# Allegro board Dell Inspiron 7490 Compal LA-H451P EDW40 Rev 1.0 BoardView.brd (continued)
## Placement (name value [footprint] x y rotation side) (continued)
CV327  220P_0201_25V7K  [C_0201]  119.01 53.18 0 top
CV390  1U_0201_6.3V6M  [C_0201]  110.88 51.73 315 top
CV391  1U_0201_6.3V6M  [C_0201]  104.26 52.87 180 top
CV392  4.7U_0201_6.3V6M  [C_0201]  109.02 50.94 225 top
CV393  4.7U_0201_6.3V6M  [C_0201]  108.2 46.64 135 top
CV394  0.1U_0201_10V6K  [C_0201]  105.95 63.86 0 top
CV395  4.7U_0201_6.3V6M  [C_0201]  104.19 67.5 45 top
CV396  22U_0603_6.3V6M  [C_0603]  106.05 64.87 45 top
CV397  0.1U_0201_10V6K  [C_0201]  122.98 38.45 225 top
CV398  0.1U_0201_10V6K  [C_0201]  103.25 63.42 270 top
CV399  1U_0201_6.3V6M  [C_0201]  97.62 62.92 90 top
CV400  1U_0201_6.3V6M  [C_0201]  103.83 48.22 45 top
CV401  1U_0201_6.3V6M  [C_0201]  103.02 49.03 45 top
CV402  1U_0201_6.3V6M  [C_0201]  104.25 47.78 45 top
CV403  10U_0402_6.3V6M  [C_0402]  98.85 39.79 180 top
CV404  10U_0402_6.3V6M  [C_0402]  98.85 38.87 180 top
CV405  22U_0603_6.3V6M  [C_0603]  99.09 37.83 180 top
CV406  22U_0603_6.3V6M  [C_0603]  101.92 51.66 0 top
CV597  10U_0603_6.3V6M  [C_0603]  16.21 47.35 270 top
CV598  0.1U_0201_16V6K  [C_0201]  15.32 46.87 270 top
CV599  0.1U_01005_10V6K  [C_01005]  21.72 42.93 180 bottom
CV600  0.1U_01005_10V6K  [C_01005]  15.58 45.23 180 top
CV601  22U_0603_6.3V6M  [C_0603]  77.74 72.91 315 top
CV602  22U_0603_6.3V6M  [C_0603]  79.47 74.66 315 top
CV603  10U_0603_6.3V6M  [C_0603]  78.6 73.8 315 top
CV604  10U_0603_6.3V6M  [C_0603]  80.35 75.51 315 top
CV605  10U_0603_6.3V6M  [C_0603]  82.34 77.49 315 top
CV606  10U_0603_6.3V6M  [C_0603]  81.49 76.64 315 top
CV607  10U_0603_6.3V6M  [C_0603]  83.2 78.34 315 top
CV608  10U_0603_6.3V6M  [C_0603]  84.06 79.17 315 top
CV609  1U_0201_6.3V6M  [C_0201]  81.74 67.76 45 bottom
CV610  1U_0201_6.3V6M  [C_0201]  88.34 75.55 270 bottom
CV611  1U_0201_6.3V6M  [C_0201]  98.77 40.54 180 top
CV612  1U_0201_6.3V6M  [C_0201]  94.11 72.21 225 bottom
CV613  1U_0201_6.3V6M  [C_0201]  88.65 65.62 135 bottom
CV614  1U_0201_6.3V6M  [C_0201]  94.64 69.69 45 bottom
CV615  1U_0201_6.3V6M  [C_0201]  87.74 66.97 45 bottom
CV616  1U_0201_6.3V6M  [C_0201]  90.14 75.46 45 bottom
CV617  1U_0201_6.3V6M  [C_0201]  87.24 73.29 270 bottom
CV618  1U_0201_6.3V6M  [C_0201]  86.72 63.5 270 bottom
CV633  2200P_0201_25V7K  [C_0201]  37.37 76.6 180 top
CV651  2200P_0201_16V7K  [C_0201]  36.04 76.6 180 top
CV701  22U_0603_6.3V6M  [C_0603]  81.9 34.23 45 top
CV702  22U_0603_6.3V6M  [C_0603]  80.18 35.95 45 top
CV703  10U_0603_6.3V6M  [C_0603]  82.75 33.39 45 top
CV704  10U_0603_6.3V6M  [C_0603]  81.03 35.1 45 top
CV705  10U_0603_6.3V6M  [C_0603]  78.25 37.87 45 top
CV706  10U_0603_6.3V6M  [C_0603]  77.4 38.71 45 top
CV707  10U_0603_6.3V6M  [C_0603]  76.55 39.57 45 top
CV708  10U_0603_6.3V6M  [C_0603]  75.7 40.42 45 top
CV709  1U_0201_6.3V6M  [C_0201]  93.4 42.98 135 bottom
CV710  1U_0201_6.3V6M  [C_0201]  83.12 45.26 315 bottom
CV711  1U_0201_6.3V6M  [C_0201]  84.54 43.84 135 bottom
CV712  1U_0201_6.3V6M  [C_0201]  85.88 45.79 315 bottom
CV713  1U_0201_6.3V6M  [C_0201]  80.55 43.29 45 bottom
CV714  1U_0201_6.3V6M  [C_0201]  78.95 42.32 315 bottom
CV715  1U_0201_6.3V6M  [C_0201]  83.79 41.42 45 bottom
CV716  1U_0201_6.3V6M  [C_0201]  85.61 44.02 315 bottom
CV717  1U_0201_6.3V6M  [C_0201]  82.84 43.06 135 bottom
CV718  1U_0201_6.3V6M  [C_0201]  86.3 47.83 90 bottom
CV741  820P_0201_25V7K  [C_0201]  79.97 37.56 225 top
CV754  820P_0201_25V7K  [C_0201]  79.58 37.95 225 top
CV755  1U_0201_6.3V6M  [C_0201]  116.17 49.62 0 top
CV756  0.1U_0201_6.3V6K  [C_0201]  98.86 65.36 315 top
CV757  0.1U_0201_6.3V6K  [C_0201]  98.95 64.37 225 top
CV759  1U_0201_6.3V6M  [C_0201]  84.58 48.06 225 bottom
CV760  1U_0201_6.3V6M  [C_0201]  94.17 41.95 135 bottom
CV761  1U_0201_6.3V6M  [C_0201]  90.78 41.32 0 bottom
CV762  1U_0201_6.3V6M  [C_0201]  86.37 49.74 315 bottom
CV763  1U_0201_6.3V6M  [C_0201]  95.81 70.75 45 bottom
CV764  1U_0201_6.3V6M  [C_0201]  86.02 65.51 270 bottom
CV765  1U_0201_6.3V6M  [C_0201]  91.69 71.26 225 bottom
CV766  1U_0201_6.3V6M  [C_0201]  92.96 72.51 45 bottom
CV767  100P_0201_25V8J  [C_0201]  114.46 51.37 135 top
CV768  0.1U_0201_6.3V6K  [C_0201]  108.63 47.04 135 top
CV769  0.1U_0201_6.3V6K  [C_0201]  109.43 50.52 225 top
CV770  100P_0201_25V8J  [C_0201]  107.45 51.87 315 top
CV771  100P_0201_25V8J  [C_0201]  104.96 63.5 270 top
CV772  100P_0201_25V8J  [C_0201]  93.57 62.75 180 top
CV773  0.1U_0201_6.3V6K  [C_0201]  93.57 63.33 180 top
CV774  0.1U_0201_10V6K  [C_0201]  105.38 66.25 45 top
CV775  100P_0201_25V8J  [C_0201]  104.99 66.67 45 top
CV776  0.1U_0201_10V6K  [C_0201]  102.87 67.9 90 top
CV777  100P_0201_25V8J  [C_0201]  102.39 65.67 315 top
CV778  0.1U_0201_10V6K  [C_0201]  98.13 65.19 225 top
CV779  100P_0201_25V8J  [C_0201]  98.52 64.77 225 top
CV780  0.1U_0201_6.3V6K  [C_0201]  102.68 63.4 270 top
CV781  10P_0201_25V8  [C_0201]  103.15 64.04 90 top
CV782  100P_0201_25V8J  [C_0201]  99.37 54.42 90 top
CV783  100P_0201_25V8J  [C_0201]  103.77 64.05 0 top
CV784  100P_0201_25V8J  [C_0201]  103.82 63.45 270 top
CV785  2200P_0201_16V7K  [C_0201]  98.76 53.67 0 top
CV786  100P_0201_25V8J  [C_0201]  120.78 51.64 90 top
CV787  0.1U_0201_6.3V6K  [C_0201]  121.35 51.64 90 top
CV788  100P_0201_25V8J  [C_0201]  116.13 51.93 270 top
CV789  100P_0201_25V8J  [C_0201]  120.06 54.96 0 top
CV930  0.1U_01005_10V6K  [C_01005]  28.11 38.81 0 top
CV931  10P_0201_25V8  [C_0201]  107.79 46.24 135 top
CV932  10P_0201_25V8  [C_0201]  98.77 41.1 180 top
CV933  10P_0201_25V8  [C_0201]  108.28 64.09 180 top
CV934  22U_0603_6.3V6M  [C_0603]  102.43 50.45 0 top
CV935  22U_0603_6.3V6M  [C_0603]  114.47 53.81 180 top
CW11  10U_0402_10V6M  [C_0402]  122.35 72.47 180 top
CW12  10P_0201_25V8  [C_0201]  122.19 73.22 180 top
CW13  0.1U_0201_10V6K  [C_0201]  137.21 77.02 270 top
CW14  1U_0201_6.3V6M  [C_0201]  138.38 77.02 270 top
CW15  10U_0402_10V6M  [C_0402]  139.13 77.19 270 top
CW16  10P_0201_25V8  [C_0201]  122.19 74.39 180 top
CW17  0.1U_0201_10V6K  [C_0201]  137.79 77.02 270 top
CW18  1U_0201_6.3V6M  [C_0201]  122.19 73.8 180 top
CZ1  1U_0201_6.3V6M  [C_0201]  142.21 29.15 180 bottom
CZ2  1U_0201_6.3V6M  [C_0201]  142.2 27.82 180 bottom
CZ3  0.1U_0201_10V6K  [C_0201]  142.21 29.71 180 bottom
CZ4  0.1U_0201_10V6K  [C_0201]  142.21 28.59 180 bottom
CZ5  0.1U_0201_10V6K  [C_0201]  146.69 30.36 0 bottom
CZ6  1000P_0201_16V7K  [C_0201]  146.69 29.8 0 bottom
CZ7  220P_0201_25V7K  [C_0201]  146.69 29.24 0 bottom
CZ8  0.1U_0201_10V6K  [C_0201]  146.71 27.82 0 bottom
CZ9  1U_0201_6.3V6M  [C_0201]  114.6 29.49 0 top
CZ10  1U_0201_6.3V6M  [C_0201]  113.22 29.49 180 top
CZ11  0.1U_0201_10V6K  [C_0201]  102.26 21.44 270 top
CZ12  0.1U_0201_10V6K  [C_0201]  112.33 24.6 180 top
CZ13  1U_0201_6.3V6M  [C_0201]  89.54 23.41 180 top
CZ14  1U_0201_6.3V6M  [C_0201]  91.94 22.72 270 top
CZ15  0.1U_0201_10V6K  [C_0201]  90.52 27.6 90 top
CZ16  470P_0201_25V7K  [C_0201]  91.07 27.6 90 top
CZ17  4700P_0402_25V7K  [C_0402]  91.81 27.64 90 top
CZ18  0.1U_0201_10V6K  [C_0201]  92.57 27.63 90 top
CZ19  1U_0201_6.3V6M  [C_0201]  121.02 48.76 90 bottom
CZ20  0.1U_0201_10V6K  [C_0201]  121.65 48.76 90 bottom
CZ21  1U_0201_6.3V6M  [C_0201]  123.6 48.13 270 bottom
CZ22  1000P_0201_16V7K  [C_0201]  122.64 44.26 0 bottom
CZ23  0.1U_0201_10V6K  [C_0201]  122.64 43.13 0 bottom
CZ38  1U_0201_6.3V6M  [C_0201]  154.97 61.6 180 top
CZ39  1U_0201_6.3V6M  [C_0201]  153.2 61.58 0 top
CZ40  0.1U_0201_10V6K  [C_0201]  148.29 49.77 180 top
CZ218  2.2U_0201_6.3V6M  [C_0201]  36.04 13.44 180 top
CZ219  0.1U_0201_10V6K  [C_0201]  151.52 60.45 180 top
CZ220  0.1U_0201_10V6K  [C_0201]  133.37 71.68 180 top
CZ221  1U_0201_6.3V6M  [C_0201]  135.17 70.2 0 top
CZ223  1U_0201_6.3V6M  [C_0201]  134.56 71.68 180 top
CZ224  1000P_0201_16V7K  [C_0201]  139 71.43 0 top
CZ225  0.1U_0201_10V6K  [C_0201]  186.9 26.92 0 top
CZ226  100P_0201_25V8J  [C_0201]  89.96 27.6 90 top
CZ227  0.1U_0201_10V6K  [C_0201]  138.7 74.25 90 top
CZ228  100P_0201_25V8J  [C_0201]  138.14 74.25 90 top
CZ229  100P_0201_25V8J  [C_0201]  122.64 43.69 0 bottom
CZ230  100P_0201_25V8J  [C_0201]  148.78 30.11 270 bottom
CZ231  100P_0201_25V8J  [C_0201]  148.15 29.23 90 bottom
CZ232  100P_0201_25V8J  [C_0201]  110.58 24.51 90 top
CZ233  100P_0201_25V8J  [C_0201]  148.94 51.23 0 top
CZ234  0.1U_0201_10V6K  [C_0201]  43.98 45.91 270 top
CZ235  1000P_0201_16V7K  [C_0201]  47 45.68 90 top
CZ236  1U_0201_6.3V6M  [C_0201]  48.01 40.63 0 top
CZ237  0.1U_0201_16V6K  [C_0201]  47.41 41.01 270 top
CZ238  10P_0201_25V8  [C_0201]  89.4 27.6 90 top
CZ239  10P_0201_25V8  [C_0201]  139.23 73.65 0 top
D2  BAT54CTB SOT-523  [BAT54CT-7-F_SOT523-3]  58.34 35.35 0 top
D3  -  [RB751S40T1G_SOD523-2]  2.39 76.15 270 bottom
D4  BAT54CTB SOT-523  [BAT54CT-7-F_SOT523-3]  35.45 62.2 270 bottom
D5  -  [RB551V-30_SOD323-2]  121.54 6.57 90 top
D8  RB751S40T1G_SOD523-2  [RB520SM-30T2R_EMD2-2]  59.35 24.95 270 top
D9  BAS516_SC79-2  [1N4148WT-7_SOD523-2]  40.54 77.41 0 top
D462  -  [RB751S40T1G_SOD523-2]  38.9 33.96 0 top
D463  BAT54CTB SOT-523  [BAT54CT-7-F_SOT523-3]  35.73 67.53 0 top
D464  -  [RB751S40T1G_SOD523-2]  15.06 68.81 90 top
D465  -  [RB751S40T1G_SOD523-2]  13.87 70.31 270 top
DB3  -  [RB520SM-30T2R_EMD2-2]  25.67 7.72 180 bottom
DB4  -  [BAT54HT1G_SOD323-2]  24.56 4.37 90 bottom
DS1  PUSB3F96_DFN2510A-10-10-X  [AZ1045-04F_DFN2510P10E-10-9]  25.33 4.75 90 top
DT4  CEST23NC24VU 3P C/A SOT23 BATT  [L30ESD24VC3-2_SOT23-3]  16.47 58.2 90 top
DT5  -  [DESD3V3Z1BCSF-7_X2-DSN0603-2-2]  12.91 64.58 270 bottom
DT6  -  [DESD3V3Z1BCSF-7_X2-DSN0603-2-2]  12.91 65.16 90 bottom
DT9  -  [DESD3V3Z1BCSF-7_X2-DSN0603-2-2]  12.91 68.51 270 bottom
DT10  -  [DESD3V3Z1BCSF-7_X2-DSN0603-2-2]  12.91 69.1 90 bottom
DT13  -  [DESD3V3Z1BCSF-7_X2-DSN0603-2-2]  12.91 62.61 270 bottom
DT14  -  [DESD3V3Z1BCSF-7_X2-DSN0603-2-2]  12.91 63.19 90 bottom
DT17  -  [DESD3V3Z1BCSF-7_X2-DSN0603-2-2]  12.91 67.13 90 bottom
DT18  -  [DESD3V3Z1BCSF-7_X2-DSN0603-2-2]  12.91 66.54 270 bottom
DT39  PUSB3F96_DFN2510A-10-10-X  [AZ1045-04F_DFN2510P10E-10-9]  14.75 62.07 90 top
DT40  PUSB3F96_DFN2510A-10-10-X  [AZ1045-04F_DFN2510P10E-10-9]  14.75 65.64 90 top
DV1  RB751S40_SOD523-2  [AZ5125-01HPR7G_SOD523-2]  131.24 66.13 180 top
DV3  RB751S40T1G SOD-523  [RB751S40T1G_SOD523-2]  122.47 40.99 90 top
DV4  RB751S40T1G SOD-523  [RB751S40T1G_SOD523-2]  118.24 44.08 135 top
DV5  RB751S40T1G SOD-523  [RB751S40T1G_SOD523-2]  117.05 43.52 135 top
DV10  RB751S40T1G SOD-523  [RB751S40T1G_SOD523-2]  102.08 77.4 270 top
DV11  RB751S40T1G SOD-523  [RB751S40T1G_SOD523-2]  115.51 48.89 315 top
DV12  RB751S40T1G SOD-523  [RB751S40T1G_SOD523-2]  115.65 47.07 135 top
DV13  RB751S40T1G_SOD523-2  [RB520SM-30T2R_EMD2-2]  36.94 75.78 270 top
DV14  RB751S40T1G_SOD523-2  [RB520SM-30T2R_EMD2-2]  35.76 75.78 270 top
DZ1  -  [RB751S40T1G_SOD523-2]  133.64 55.97 0 top
DZ2  RB751S40T1G_SOD523-2  [RB520SM-30T2R_EMD2-2]  119.61 50.32 0 bottom
DZ5  -  [RB751S40T1G_SOD523-2]  140.61 28.89 90 bottom
DZ6  -  [RB751S40T1G_SOD523-2]  103.75 20.35 90 top
DZ7  RB751S40T1G_SOD523-2  [RB520SM-30T2R_EMD2-2]  185.56 27.88 0 top
DZ12  RB751S40T1G_SOD523-2  [RB520SM-30T2R_EMD2-2]  36.82 16.72 180 top
EC2  0.1U_0201_16V6K  [C_0201]  3.89 74.13 180 bottom
ED4  CEST523NC5VB 3P C/A SOT-523 AU  [L03ESDL5V0CG3-2_SOT-523-3]  35.1 69.41 180 bottom
ED10  AZ5123-02S.R7G_SOT23-3  [AZ5123-02SPR7G_SOT23-3]  110.71 5.72 0 top
ED11  PUSB3F96_DFN2510A-10-10-X  [AZ1045-04F_DFN2510P10E-10-9]  93.3 10.85 180 bottom
ED12  PUSB3F96_DFN2510A-10-10-X  [AZ1045-04F_DFN2510P10E-10-9]  31.62 69.07 0 bottom
EU6  CEST523NC5VB 3P C/A SOT-523 AU  [L03ESDL5V0CG3-2_SOT-523-3]  89.87 12.85 180 bottom
F1  3A_32V_F0603FA3000V032T  [F_F0603FA3000V032T]  37.03 69.1 0 top
F2  2A_65V_T0603FF2000TM  [F_T0603FF1000TM]  44.08 70.69 180 top
F3  0.5A_6V_0402L050SLKR  [F_0402L050SLKR]  39.2 8.39 0 top
F4  1A_65V_T0603FF1000TM  [F_T0603FF1000TM]  38.22 75.24 270 top
F5  0.5A_65V_T0603FF0500TM  [F_T0603FF0500TM]  42.33 50.94 180 top
F6  0.5A_65V_T0603FF0500TM  [F_T0603FF0500TM]  29.71 70.99 90 top
F7  0.5A_65V_T0603FF0500TM  [F_T0603FF0500TM]  31.11 70.63 90 top
F8  0.5A_65V_T0603FF0500TM  [F_T0603FF0500TM]  41.3 55.97 270 top
F9  0.5A_65V_T0603FF0500TM  [F_T0603FF0500TM]  46.64 56.66 90 top
FD1  FIDUCAL  [FIDUCIAL_C40M80]  190.72 23.4 0 top
FD2  FIDUCAL  [FIDUCIAL_C40M80]  22.33 75.82 0 top
FD3  FIDUCAL  [FIDUCIAL_C40M80]  189.22 75.17 180 bottom
FD4  FIDUCAL  [FIDUCIAL_C40M80]  28.31 6.58 180 bottom
H1  HOLEA  [H_1P8N]  7.25 33 0 top
H2  HOLEA  [H_3P6]  156.89 6.25 0 top
H4  HOLEA  [H_3P3]  34.09 25.78 0 top
H5  HOLEA  [H_3P7-G]  191.45 32.95 0 top
H6  HOLEA  [H_3P6-G]  214.95 7 0 top
H7  HOLEA  [H_3P7-G]  127.95 30 0 top
H8  HOLEA  [H_4P1X3P6-G]  194.14 76.01 90 top
H9  HOLEA  [H_2P8-G]  19.95 5 0 top
H10  HOLEA  [H_2P6-G]  8.95 75.5 0 top
H11  HOLEA  [H_3P4]  79.15 58 0 top
H12  HOLEA  [H_2P6-G]  8.95 56.5 0 top
H13  HOLEA  [H_3P6X4P1-G]  126 59.5 90 top
H16  HOLEA  [H_3P3]  56.03 11.4 0 top
H17  HOLEA  [H_3P7N]  84.1 25.78 0 top
H18  HOLEA  [H_3P3]  45.95 76.5 0 top
H19  HOLEA  [H_3P3]  26.45 68 0 top
H20  HOLEA  [H_2P0X1P6N]  213.35 17.5 0 top
H35  -  [H_0P5X2P3N]  75.85 61.91 180 bottom
H36  -  [H_0P5X2P3N]  148.34 15.1 90 bottom
H37  -  [H_0P5X2P3N]  152.85 15.1 90 bottom
H38  -  [H_0P5X2P3N]  210.55 6.9 180 bottom
H39  -  [H_0P5X2P3N]  198.2 76.9 180 bottom
H40  -  [H_0P5X2P3N]  169.85 79.3 90 bottom
H41  -  [H_0P5X2P3N]  137.35 79.3 90 bottom
H42  HOLEA  [H_2P6]  118.45 79.9 0 top
JANT1  BELLW_10093-1021  [BELLW_10093-1021_4P]  71.35 77.63 180 bottom
JANT2  I-PEX_20854-005E-00  [I-PEX_20854-005E-00_5P-T]  37.92 67.6 90 bottom
JAPS1  ACES_50506-01841-P01  [ACES_50506-01841-P01_18P-NPM]  133.95 72.83 180 top
JCAM1  ACES_50100-0127N-001  [ACES_50100-0127N-001_12P]  15.05 70 270 bottom
JDB2  ACES_50521-01041-P01  [ACES_50521-01041-P01_10P]  25.4 10.65 0 top
JDEG1  -  [ACES_50521-01041-P01_10P]  32.35 5.49 0 top
JEDP1  I-PEX_20879-040E-01  [I-PEX_20879-040E-01_40P-T]  40.75 72.32 0 bottom
JESPI1  ACES_50521-01041-P01_10P  [ACES_50521-01041-P01_10P-NPM]  39.75 5.49 0 top
JFP1  TWVM_FPC0510-08RC-TAGHA  [TWVM_FPC0510-08RC-TAGHA_8P]  90.8 9.2 180 bottom
JHDMI1  ACON_HMRF6-AK120D  [ACON_HMRF6-AK120D_19P-T]  11.31 39 90 bottom
JIO1  I-PEX_20849-040E-01  [I-PEX_20849-040E-01_40P-T]  195.49 7.75 90 top
JIO2  ACES_50279-0040C-P01  [ACES_50279-0040C-P01_4P]  138.7 10.22 270 bottom
JKB1  STARC_132C30-100020-A2-R  [STARC_132C30-100020-A2-R_30P]  81.65 8.14 180 bottom
JKBBL1  ACES_51575-00401-001  [ACES_51575-00401-001_4P]  38.7 9.24 180 bottom
JNGFF1  LOTES_APCI0144-P007A  [LOTES_APCI0144-P007A_75P]  65.26 57.08 180 bottom
JP3  -  [JUMP_43X79]  112.93 23.18 270 top
JREAD1  T-SOL_158-1000902603  [T-SOL_158-1000902603_9P]  1.31 20.26 270 top
JRTC1  ACES_50278-00201-001  [ACES_50278-00201-001_2P]  2.7 5.5 270 bottom
JSIM1  T-SOL_5-501901001000-6  [T-SOL_5-501901001000-6_15P-T]  5.78 6.25 270 top
JSPI1  -  [ACES_50521-01041-P01_10P]  50.2 8.75 180 bottom
JSSD1  LOTES_APCI0146-P004A  [LOTES_APCI0146-P004A_75P]  117.62 16.52 90 bottom
JTP1  ACES_51524-0080N-001  [ACES_51524-0080N-001_8P]  132.55 11.45 180 bottom
JUSBC1  FOX_UT12123-1A602-7H  [FOX_UT12123-1A602-7H_24P-T]  9.34 63.38 90 bottom
JXDP1  JXT_FP270H-061G1AM  [JXT_FP270H-061G1AM_61P-NPM]  123.73 6.77 0 top
L3  DLM0NSN900HY2D_4P  [MURAT_DLM0NSN900HY2D_4P]  32.15 66.37 90 bottom
L16  BLM15PX471SN1D_2P  [MURAT_BLM15PX471SN1D_2P]  129.7 50.08 0 bottom
LC3  BLM18EG221TN1D_2P  [CHILI_PBY160808T-300Y-N_2P]  141.33 35.64 90 top
LC4  BLM18EG221TN1D_2P  [MURAT_BLM18EG221TN1D_2P-S]  142.71 47.39 0 top
LC5  BLM15BD121SN1D_2P~D  [MURAT_BLM15BD121SN1D_2P]  132.45 32.45 270 bottom
LED1  12-22A/Y2T7D-C30/2C YELLOW/WHITE  [LED_12-22A-S2ST3D-C30-2C_3P]  3.5 54.9 270 bottom
LFP4  DLM0NSN900HY2D_4P  [MURAT_DLM0NSN900HY2D_4P-NPM]  94.78 13.02 180 bottom
LI1  HCM1012GH900BP_4P  [INPAQ_HCM1012GH900BP_4P-NPM]  16.64 44.38 0 top
LI2  HCM1012GH900BP_4P  [INPAQ_HCM1012GH900BP_4P-NPM]  16.64 42.76 0 top
LI3  HCM1012GH900BP_4P  [INPAQ_HCM1012GH900BP_4P-NPM]  16.64 39.51 0 top
LI4  HCM1012GH900BP_4P  [INPAQ_HCM1012GH900BP_4P-NPM]  16.64 41.13 0 top
LIO1  DLM0NSN900HY2D_4P  [MURAT_DLM0NSN900HY2D_4P]  192.05 17.44 0 top
LIO2  DLM0NSN900HY2D_4P  [MURAT_DLM0NSN900HY2D_4P]  192.05 18.91 0 top
LM1  PBY160808T-300Y-N_2P  [CHILI_PBY160808T-300Y-N_2P]  21.6 44.91 0 bottom
LM2  PBY160808T-300Y-N_2P  [CHILI_PBY160808T-300Y-N_2P]  19.54 38.14 90 bottom
LM3  PBY160808T-300Y-N_2P  [CHILI_PBY160808T-300Y-N_2P]  16.59 38.14 90 bottom
LM4  PBY160808T-300Y-N_2P  [CHILI_PBY160808T-300Y-N_2P]  21.86 38.15 90 bottom
LM5  PBY160808T-300Y-N_2P  [CHILI_PBY160808T-300Y-N_2P]  18.08 38.14 90 bottom
LN3  HCM1012GH900BP_4P  [INPAQ_HCM1012GH900BP_4P-NPM]  51.76 53.66 90 top
LN9  CHILISIN SBY100505T-121Y-N  [MURAT_BLM15AG121SN1D_L0402_2P]  41.54 65.5 180 bottom
LN10  CHILISIN SBY100505T-121Y-N  [MURAT_BLM15AG121SN1D_L0402_2P]  43.7 69.66 180 bottom
LN18  HCM1012GH900BP_4P  [INPAQ_HCM1012GH900BP_4P-NPM]  55.27 57.81 270 top
LN19  HCM1012GH900BP_4P  [INPAQ_HCM1012GH900BP_4P-NPM]  53.29 53.66 90 top
LS4  150NH_BSCH00100505R15JCS_5%  [MURAT_LQG15HSR15J02D_2P]  71.76 76.23 0 top
LT2  1UH_LQM18PN1R0MFHD_20%  [MURAT_LQM18NN1R0K00D_2P]  22.98 59.14 90 top
LT10  0.6UH_MND-04ABIR60M-XGL_20%  [MAG_MND-04ABIR60M-XGL_2P]  33.67 66.82 180 top
LT11  HCB2012KF-800T50_2P  [TAI-T_HCB2012KF-121T50_2P]  32.69 32.65 180 top
LT13  HCB2012KF-800T50_2P  [TAI-T_HCB2012KF-121T50_2P]  32.69 30.88 180 top
LU3  DLM0NSN900HY2D_4P  [MURAT_DLM0NSN900HY2D_4P]  16.26 66.14 0 top
LU4  DLM0NSN900HY2D_4P  [MURAT_DLM0NSN900HY2D_4P]  16.26 64.07 0 top
LV7  BLM15PD300SN1D_2P  [TAI-T_HCB1005KF-300T25_2P]  101.93 62.98 90 top
LV10  BLM15PD300SN1D_2P  [TAI-T_HCB1005KF-300T25_2P]  103.14 66.09 45 top
NOREF  -  []  204.48 9.87 0 top
NOREF#2  -  []  125.99 59.5 90 top
NOREF#3  -  []  8.95 75.5 0 top
NOREF#4  -  []  111.72 -32.05 0 top
NOREF#5  -  []  34.09 25.78 0 top
NOREF#6  -  []  156.89 6.25 0 top
NOREF#7  -  []  191.45 32.95 0 top
NOREF#8  -  []  164.33 23.81 0 top
NOREF#9  -  []  56.03 11.4 0 top
NOREF#10  -  []  26.45 68 0 top
NOREF#11  -  []  45.95 76.5 0 top
NOREF#12  -  []  127.95 30 0 top
NOREF#13  -  []  214.95 7 0 top
NOREF#14  -  []  19.95 5 0 top
NOREF#15  -  []  282.17 -27.89 0 top
NOREF#16  -  []  174.21 60.1 0 top
NOREF#17  -  []  79.15 58 0 top
NOREF#18  -  []  194.14 76.01 0 top
NOREF#19  -  []  8.95 56.5 0 top
NOREF#20  -  []  60.73 -32.86 180 bottom
NOREF#21  -  []  43.73 21.22 180 bottom
PBATT1  ACES_50278-01201-001  [ACES_50278-01201-001_12P-T]  116.95 11.85 180 bottom
PC11  100P_0402_50V8J  [C_0402]  99.3 8.32 270 top
PC12  1000P_0402_50V7K  [C_0402]  106.9 11.62 270 top
PC17  100P_0402_50V8J  [C_0402]  107.78 11.62 270 top
PC23  1000P_0402_50V7K  [C_0402]  100.19 8.32 270 top
PC100  .1U_0402_16V7K  [C_0402]  100.16 25.9 90 top
PC301  1000P_0402_25V8J  [C_0402]  8.77 19.6 180 bottom
PC302  2200P_0402_50V7K  [C_0402]  11.64 11.85 0 bottom
PC303  10U_0603_25V6M  [C_0603]  9.99 13.1 180 bottom
PC304  10U_0603_25V6M  [C_0603]  9.99 11.9 180 bottom
PC305  0.1U_0402_25V6  [C_0402]  11.16 14.33 90 bottom
PC306  1U_0402_25V6K  [C_0402]  8.77 20.49 180 bottom
PC307  .1U_0402_16V7K  [C_0402]  15.98 11.75 0 bottom
PC308  4.7U_0402_6.3V6M  [C_0402]  15.54 18.11 0 bottom
PC309  680P_0402_50V7K  [C_0402]  19.93 15.56 90 top
PC310  22U_0603_6.3V6M  [C_0603]  23.11 16.69 180 top
PC311  22U_0603_6.3V6M  [C_0603]  23.11 13.1 180 top
PC312  22U_0603_6.3V6M  [C_0603]  23.11 15.49 180 top
PC313  22U_0603_6.3V6M  [C_0603]  23.11 14.3 180 top
PC315  1000P_0402_25V8J  [C_0402]  13.56 18.07 90 bottom
PC317  2200P_0201_10V6K  [C_0201]  24.42 16.86 90 top
PC318  0.1U_0201_6.3V6K  [C_0201]  23.86 16.86 90 top
PC319  100P_0201_25V7K  [C_0201]  24.99 16.86 90 top
PC321  100P_0201_50V8J  [C_0201]  13.26 12.18 270 bottom
PC501  33U_B3_16VM_R45M  [C_B3]  9.94 26.52 90 bottom
PC502  0.1U_0402_25V6  [C_0402]  12.89 28.81 90 bottom
PC503  2200P_0402_50V7K  [C_0402]  12 28.81 90 bottom
PC504  10U_0603_25V6M  [C_0603]  9.72 23.28 90 bottom
PC505  10U_0603_25V6M  [C_0603]  10.91 23.28 90 bottom
PC506  22U_0603_6.3V6M  [C_0603]  21.51 20.46 270 top
PC507  22U_0603_6.3V6M  [C_0603]  22.68 25.68 90 top
PC508  22U_0603_6.3V6M  [C_0603]  25.2 20.52 270 top
PC509  22U_0603_6.3V6M  [C_0603]  23.91 25.67 90 top
PC510  22U_0603_6.3V6M  [C_0603]  23.95 20.5 270 top
PC511  22U_0603_6.3V6M  [C_0603]  22.72 20.48 270 top
PC513  2.2U_0402_6.3V6M  [C_0402]  13.24 27.28 0 bottom
PC514  0.22U_0402_16V7K  [C_0402]  15.58 19.04 0 bottom
PC515  220P_0201_25V7K  [C_0201]  13.14 19.78 180 bottom
PC516  680P_0603_50V8J  [C_0603]  18 23.85 0 top
PC517  100P_0201_50V8J  [C_0201]  8.04 27.84 90 bottom
PC518  2200P_0201_10V6K  [C_0201]  26.81 20.18 270 top
PC519  0.1U_0201_6.3V6K  [C_0201]  26.15 20.18 270 top
PC520  100P_0201_25V7K  [C_0201]  24.96 25.8 90 top
PC532  4.7U_0402_6.3V6M  [C_0402]  50.12 7.63 180 top
PC533  1000P_0402_25V8J  [C_0402]  8.77 18.71 180 bottom
PC534  1U_0402_25V6K  [C_0402]  8.77 17.82 180 bottom
PC535  1000P_0402_25V8J  [C_0402]  137.05 12.68 180 bottom
PC536  1U_0402_25V6K  [C_0402]  137.05 13.62 180 bottom
PC537  0.1U_0402_25V6  [C_0402]  137.05 11.74 180 bottom
PC538  100P_0201_50V8J  [C_0201]  136.91 10.97 180 bottom
PC1801  10U_0603_25V6M  [C_0603]  71.2 17.12 0 top
PC1802  10U_0603_25V6M  [C_0603]  71.22 18.38 0 top
PC1803  0.1U_0402_25V6  [C_0402]  71.15 15.15 0 top
PC1804  2200P_0402_25V7K  [C_0402]  71.15 16.06 0 top
PC1805  22U_0603_6.3V6M  [C_0603]  78.13 24.48 270 top
PC1806  22U_0603_6.3V6M  [C_0603]  75.74 24.48 270 top
PC1807  22U_0603_6.3V6M  [C_0603]  79.32 24.48 270 top
PC1808  22U_0603_6.3V6M  [C_0603]  76.94 24.48 270 top
PC1809  2.2U_0402_6.3V6M  [C_0402]  68.78 22.09 270 top
PC1810  0.22U_0402_16V7K  [C_0402]  67.8 24.91 90 top
PC1811  220P_0201_25V7K  [C_0201]  66.68 19.65 0 top
PC1812  680P_0603_50V8J  [C_0603]  72.55 28.04 90 top
PC1813  0.1U_0402_25V6  [C_0402]  69.81 17.9 270 top
PC1814  1000P_0402_25V8J  [C_0402]  70.84 11.83 270 top
PC1815  1U_0402_25V6K  [C_0402]  71.73 11.83 270 top
PC1816  .1U_0402_16V7K  [C_0402]  111.28 16.85 90 top
PC1817  100P_0201_50V8J  [C_0201]  70.45 18.76 180 top
PC1818  0.1U_0201_6.3V6K  [C_0201]  73.47 27.85 90 top
PC1819  100P_0201_25V7K  [C_0201]  74.07 27.85 90 top
PCA02  10U_0603_25V6M  [C_0603]  143 16.67 0 bottom
PCA03  10U_0603_25V6M  [C_0603]  140.42 17.11 90 bottom
PCA04  1U_0402_25V6K  [C_0402]  141.5 22.2 180 bottom
PCA05  0.1U_0402_25V7K  [C_0402]  143.66 17.74 90 top
PCA06  2200P_0402_50V7K  [C_0402]  144.59 17.74 90 top
PCA08  1U_0402_6.3V6K  [C_0402]  140.6 20.39 270 bottom
PCA09  0.22U_0402_16V7K  [C_0402]  140.65 21.26 180 bottom
PCA10  680P_0402_50V7K  [C_0402]  146.25 23.88 0 top
PCA11  1000P_0402_25V8J  [C_0402]  137.77 18.89 0 bottom
PCA12  1U_0402_25V6K  [C_0402]  136.76 18.84 90 bottom
PCA100  22U_0603_6.3V6M  [C_0603]  150.09 47.37 0 top
PCA102  22U_0603_6.3V6M  [C_0603]  150.35 40.18 0 top
PCA103  22U_0603_6.3V6M  [C_0603]  150.09 46.17 0 top
PCA104  22U_0603_6.3V6M  [C_0603]  148.51 38.49 180 top
PCA105  22U_0603_6.3V6M  [C_0603]  150.09 44.98 0 top
PCA106  22U_0603_6.3V6M  [C_0603]  149.34 41.39 180 top
PCA107  22U_0603_6.3V6M  [C_0603]  150.09 43.79 0 top
PCA108  22U_0603_6.3V6M  [C_0603]  150.09 42.59 0 top
PCA109  22U_0603_6.3V6M  [C_0603]  150.28 41.4 0 top
PCA110  22U_0603_6.3V6M  [C_0603]  149.58 35.9 0 top
PCA111  22U_0603_6.3V6M  [C_0603]  149.58 37.12 0 top
PCA112  22U_0603_6.3V6M  [C_0603]  149.39 40.19 180 top
PCA113  1U_0201_6.3V6M  [C_0201]  150.12 38.64 0 top
PCA114  1U_0201_6.3V6M  [C_0201]  150.14 51.23 0 top
PCA115  1U_0201_6.3V6M  [C_0201]  150.14 50.59 0 top
PCA116  1U_0201_6.3V6M  [C_0201]  149.29 43.61 180 top
PCA117  1U_0201_6.3V6M  [C_0201]  149.29 43.04 180 top
PCA118  1U_0201_6.3V6M  [C_0201]  149.29 42.47 180 top
PCA119  1U_0201_6.3V6M  [C_0201]  150.78 49.51 0 top
PCB01  0.1U_0402_25V6  [C_0402]  190.3 8.37 0 top
PCB02  2200P_0402_50V7K  [C_0402]  190.3 9.26 0 top
PCB03  10U_0603_25V6M  [C_0603]  190.06 11.5 0 top
PCB04  10U_0603_25V6M  [C_0603]  192.96 14.44 0 bottom
PCB05  10U_0603_25V6M  [C_0603]  192.96 13.24 0 bottom
PCB06  10U_0603_25V6M  [C_0603]  190.06 12.69 0 top
PCB07  33U_B3_16VM_R45M  [C_B3]  95.87 15.47 90 top
PCB10  10U_0603_25V6M  [C_0603]  205.01 26.43 0 bottom
PCB11  10U_0603_25V6M  [C_0603]  204.32 28.11 0 bottom
PCB12  10U_0603_25V6M  [C_0603]  205 24.02 0 bottom
PCB13  10U_0603_25V6M  [C_0603]  206.79 29.59 270 bottom
PCB14  10U_0603_25V6M  [C_0603]  205.01 25.23 0 bottom
PCB15  10U_0603_25V6M  [C_0603]  204.32 29.31 0 bottom
PCB16  10U_0603_25V6M  [C_0603]  190.06 10.3 0 top
PCB17  10U_0603_25V6M  [C_0603]  192.02 13.24 180 bottom
PCB18  4.7U_0402_6.3V6M  [C_0402]  194.94 20.35 0 bottom
PCB19  1U_0402_25V6K  [C_0402]  194.91 19.46 270 bottom
PCB20  1U_0402_25V6K  [C_0402]  195.82 19.47 270 bottom
PCB21  0.1U_0402_25V6  [C_0402]  203.64 23.84 180 bottom
PCB22  2200P_0402_50V7K  [C_0402]  201.6 29.32 180 bottom
PCB23  1U_0402_25V6K  [C_0402]  201.03 17.42 270 bottom
PCB24  1000P_0402_50V7K  [C_0402]  201.77 30.26 180 bottom
PCB25  0.47U_0402_25V6K  [C_0402]  199.2 18.7 90 bottom
PCB26  0.1U_0402_25V6  [C_0402]  190.39 22.28 180 bottom
PCB27  2.2U_0402_25V6M  [C_0402]  192.23 19.54 270 bottom
PCB28  2.2U_0402_25V6M  [C_0402]  192.41 21.19 180 bottom
PCB29  2.2U_0402_25V6M  [C_0402]  200.11 20.78 0 bottom
PCB30  0.47U_0402_25V6K  [C_0402]  200.11 22.87 0 bottom
PCB31  10U_0603_25V6M  [C_0603]  93.6 11.61 270 top
PCB32  10U_0603_25V6M  [C_0603]  92.35 11.62 270 top
PCB33  4700P_0402_25V7K  [C_0402]  95.44 9.26 180 top
PCB34  10P_0402_50V8J  [C_0402]  193.16 27.68 90 bottom
PCB35  0.1U_0402_25V6  [C_0402]  200.49 23.76 0 bottom
PCB36  680P_0402_50V7K  [C_0402]  196.13 16.64 180 bottom
PCB37  680P_0402_50V7K  [C_0402]  204.19 17.34 270 bottom
PCB38  1U_0402_25V6K  [C_0402]  200.82 25.44 0 bottom
PCB39  560P_0402_50V7K  [C_0402]  195.89 27.7 90 bottom
PCB40  0.1U_0402_25V6  [C_0402]  197.85 28.5 90 bottom
PCB41  1U_0402_25V6K  [C_0402]  199.96 25.61 90 bottom
PCB42  0.01UF_0402_25V7K  [C_0402]  197.82 30.27 0 bottom
PCB43  0.22U_0402_25V6K  [C_0402]  200.82 27.09 0 bottom
PCB45  0.1U_0402_25V6  [C_0402]  198.98 27.29 90 bottom
PCB46  82P_0402_50V8J  [C_0402]  203.67 24.73 180 bottom
PCB47  10U_0603_25V6M  [C_0603]  192.02 14.44 180 bottom
PCB48  100P_0201_50V8J  [C_0201]  190.47 7.65 0 top
PCB49  100P_0201_50V8J  [C_0201]  203.58 25.49 180 bottom
PCB50  10P_0402_50V8J  [C_0402]  201.95 17.42 270 bottom
PCB51  33U_B3_16VM_R45M  [C_B3]  102.26 13.73 90 top
PCF01  1U_0402_6.3V6K  [C_0402]  118.33 42.36 0 bottom
PCF02  22U_0402_6.3V6M  [C_0402]  118.53 47.14 0 bottom
PCF03  0.1U_0402_10V6K  [C_0402]  117.21 41.56 180 bottom
PCF04  0.01U_0402_25V7K  [C_0402]  109.94 43.4 270 bottom
PCF05  22U_0603_6.3V6M  [C_0603]  111.88 43.35 90 bottom
PCF06  2200P_0201_10V6K  [C_0201]  108.6 42.04 270 bottom
PCF07  0.1U_0201_6.3V6K  [C_0201]  107.99 42.06 270 bottom
PCF08  100P_0201_25V7K  [C_0201]  107.33 42.04 270 bottom
PCF09  220P_0402_25V8J  [C_0402]  112.76 41.19 0 bottom
PCG02  10U_0603_25V6M  [C_0603]  204.22 35.3 0 bottom
PCG03  10U_0603_25V6M  [C_0603]  204.51 37.67 90 bottom
PCG04  1U_0402_25V6K  [C_0402]  198.79 36.51 270 bottom
PCG05  0.1U_0402_25V6  [C_0402]  204.41 37.81 90 top
PCG06  2200P_0402_50V7K  [C_0402]  205.32 37.81 90 top
PCG07  1U_0402_6.3V6K  [C_0402]  201.16 35.12 0 bottom
PCG08  0.22U_0402_16V7K  [C_0402]  199.56 34.69 180 bottom
PCG09  680P_0402_50V7K  [C_0402]  197.09 46.87 0 bottom
PCG10  1000P_0402_25V8J  [C_0402]  203.35 28.08 180 bottom
PCG11  1U_0402_25V6K  [C_0402]  203.35 28.97 180 bottom
PCG20  33U_B3_16VM_R45M  [C_B3]  201.93 32.32 180 bottom
PCG100  22U_0603_6.3V6M  [C_0603]  178.18 42.78 270 top
PCG101  47U_0603_6.3V6M  [C_0603]  181.56 47.32 0 bottom
PCG102  47U_0603_6.3V6M  [C_0603]  181.56 44.83 0 bottom
PCG103  47U_0603_6.3V6M  [C_0603]  181.56 46.08 0 bottom
PCG104  47U_0603_6.3V6M  [C_0603]  181.56 43.56 0 bottom
PCG105  47U_0603_6.3V6M  [C_0603]  184.07 42.22 90 bottom
PCG106  47U_0603_6.3V6M  [C_0603]  185.32 42.24 90 bottom
PCG107  47U_0603_6.3V6M  [C_0603]  172.78 39.27 180 top
PCG108  22U_0603_6.3V6M  [C_0603]  176.5 38.4 90 top
PCG109  22U_0603_6.3V6M  [C_0603]  179.84 42.78 270 top
PCG110  47U_0603_6.3V6M  [C_0603]  176.38 45.5 270 top
PCG111  47U_0603_6.3V6M  [C_0603]  178.21 45.5 270 top
PCG112  47U_0603_6.3V6M  [C_0603]  173.27 48.06 180 top
PCG113  22U_0603_6.3V6M  [C_0603]  181.06 45.94 0 top
PCG114  22U_0603_6.3V6M  [C_0603]  170.8 48.06 180 top
PCG115  22U_0603_6.3V6M  [C_0603]  170.8 46.86 180 top
PCG116  22U_0603_6.3V6M  [C_0603]  170.8 45.67 180 top
PCG117  22U_0603_6.3V6M  [C_0603]  170.8 44.47 180 top
PCG118  22U_0603_6.3V6M  [C_0603]  170.8 43.28 180 top
PCG119  22U_0603_6.3V6M  [C_0603]  173.27 43.28 180 top
PCG120  22U_0603_6.3V6M  [C_0603]  173.27 44.47 180 top
PCG121  47U_0603_6.3V6M  [C_0603]  173.27 45.67 180 top
PCG122  47U_0603_6.3V6M  [C_0603]  173.27 46.86 180 top
PCG123  22U_0603_6.3V6M  [C_0603]  187.82 42.29 90 bottom
PCG124  22U_0603_6.3V6M  [C_0603]  176.38 42.76 270 top
PCG125  22U_0603_6.3V6M  [C_0603]  179.84 45.53 270 top
PCG126  22U_0603_6.3V6M  [C_0603]  181.06 47.14 0 top
PCG127  22U_0603_6.3V6M  [C_0603]  181.06 44.75 0 top
PCG128  22U_0603_6.3V6M  [C_0603]  181.68 40.37 270 bottom
PCG129  22U_0603_6.3V6M  [C_0603]  186.55 42.25 90 bottom
PCG130  22U_0603_6.3V6M  [C_0603]  169.74 41.01 270 top
PCG131  22U_0603_6.3V6M  [C_0603]  174.57 38 90 top
PCG132  22U_0603_6.3V6M  [C_0603]  170.8 49.25 180 top
PCG133  22U_0603_6.3V6M  [C_0603]  176.25 47.48 90 top
PCG134  22U_0603_6.3V6M  [C_0603]  177.45 47.48 90 top
PCG135  22U_0603_6.3V6M  [C_0603]  178.64 47.48 90 top
PCG136  22U_0603_6.3V6M  [C_0603]  179.84 47.48 90 top
PCG137  22U_0603_6.3V6M  [C_0603]  173.27 49.25 180 top
PCG138  330_B2_2.5VM_R9M  [C_B2]  187.82 39.71 90 bottom
PCG139  330_B2_2.5VM_R9M  [C_B2]  184.54 38.55 90 bottom
PCG140  1U_0201_6.3V6M  [C_0201]  170.95 40.79 270 top
PCG141  1U_0201_6.3V6M  [C_0201]  171.86 40.8 270 top
PCG142  1U_0201_6.3V6M  [C_0201]  172.8 40.8 270 top
PCG143  1U_0201_6.3V6M  [C_0201]  178.4 38.67 0 top
PCG144  1U_0201_6.3V6M  [C_0201]  178.3 39.37 0 top
PCG145  1U_0201_6.3V6M  [C_0201]  178.32 40.15 0 top
PCG146  1U_0201_6.3V6M  [C_0201]  174.79 40.31 0 top
PCG147  1U_0201_6.3V6M  [C_0201]  174.73 41.89 270 top
PCG148  1U_0201_6.3V6M  [C_0201]  175.42 41.87 270 top
PCG149  1U_0201_6.3V6M  [C_0201]  174.86 43.7 270 top
PCG150  1U_0201_6.3V6M  [C_0201]  175.49 43.7 270 top
PCG151  1U_0201_6.3V6M  [C_0201]  174.86 45.35 270 top
PCG152  1U_0201_6.3V6M  [C_0201]  175.44 45.35 270 top
PCG153  1U_0201_6.3V6M  [C_0201]  174.88 46.85 90 top
PCH01  0.1U_0402_25V6  [C_0402]  128.7 18.06 0 bottom
PCH02  0.1U_0402_25V6  [C_0402]  128.96 24.11 0 bottom
PCH03  22U_0805_25V6M  [C_0805]  129.06 25.45 0 bottom
PCH04  22U_0805_25V6M  [C_0805]  129.24 16.75 0 bottom
PCH05  47U_0603_6.3V6M  [C_0603]  137.72 28.02 0 bottom
PCH06  47U_0603_6.3V6M  [C_0603]  139.88 25.68 270 bottom
PCH07  47U_0603_6.3V6M  [C_0603]  138.46 23.23 180 top
PCH08  47U_0603_6.3V6M  [C_0603]  137.71 26.77 0 bottom
PCH09  0.1U_0402_25V6  [C_0402]  125.48 19.81 180 bottom
PCH10  0.1U_0402_25V6  [C_0402]  127.98 25.81 270 bottom
PCH11  680P_0402_50V7K  [C_0402]  136.03 21.3 180 top
PCH12  100P_0402_50V8J  [C_0402]  124.59 17.2 90 bottom
PCH13  4.7U_0402_10V6M  [C_0402]  125.47 23.05 180 bottom
PCH14  0.1U_0402_25V6  [C_0402]  125.46 20.72 180 bottom
PCH15  1000P_0402_25V8J  [C_0402]  134.83 18.86 90 bottom
PCH16  1U_0402_25V6K  [C_0402]  135.81 18.84 90 bottom
PCH17  47U_0603_6.3V6M  [C_0603]  138.48 24.5 180 top
PCH18  100P_0201_50V8J  [C_0201]  132.47 18.8 180 bottom
PCH19  2200P_0402_50V7K  [C_0402]  132.66 18.06 180 bottom
PCH20  2200P_0201_10V6K  [C_0201]  138.44 22.3 270 top
PCH21  0.1U_0201_6.3V6K  [C_0201]  137.87 22.3 270 top
PCH22  100P_0201_25V7K  [C_0201]  139.01 22.3 270 top
PCI01  33U_B3_16VM_R45M  [C_B3]  173.12 10.1 270 top
PCI02  33U_B3_16VM_R45M  [C_B3]  169.59 7.2 180 bottom
PCI04  10U_0603_25V6M  [C_0603]  169.53 9.79 0 bottom
PCI05  10U_0603_25V6M  [C_0603]  170.33 9.2 270 top
PCI06  1U_0402_25V6K  [C_0402]  168.01 15.33 180 bottom
PCI07  0.1U_0402_25V7K  [C_0402]  166.47 10.63 90 bottom
PCI08  2200P_0402_50V7K  [C_0402]  167.1 9.75 180 bottom
PCI10  1U_0402_6.3V6K  [C_0402]  166.45 13.32 270 bottom
PCI11  0.22U_0402_16V7K  [C_0402]  166.2 15.2 90 bottom
PCI12  680P_0402_50V7K  [C_0402]  170.5 19.85 0 top
PCI13  33U_B3_16VM_R45M  [C_B3]  164.91 10.07 270 top
PCI14  33U_B3_16VM_R45M  [C_B3]  177.33 7.38 180 bottom
PCI16  10U_0603_25V6M  [C_0603]  176.81 9.87 0 bottom
PCI17  10U_0603_25V6M  [C_0603]  176.15 9.18 270 top
PCI18  1U_0402_25V6K  [C_0402]  175.78 15.33 180 bottom
PCI19  0.1U_0402_25V7K  [C_0402]  177.27 9.13 270 top
PCI20  2200P_0402_50V7K  [C_0402]  174.32 10.6 90 bottom
PCI22  1U_0402_6.3V6K  [C_0402]  174.08 13.33 270 bottom
PCI23  0.22U_0402_16V7K  [C_0402]  173.98 15.2 90 bottom
PCI24  680P_0402_50V7K  [C_0402]  177.69 18.86 90 top
PCI25  33U_B3_16VM_R45M  [C_B3]  168.09 10.07 270 top
PCI28  10U_0603_25V6M  [C_0603]  179.43 9.37 270 top
PCI29  10U_0603_25V6M  [C_0603]  184.06 9.87 0 bottom
PCI30  1U_0402_25V6K  [C_0402]  183.4 15.33 180 bottom
PCI31  0.1U_0402_25V7K  [C_0402]  182.09 10.76 90 bottom
PCI32  2200P_0402_50V7K  [C_0402]  182.35 9.77 180 bottom
PCI34  1U_0402_6.3V6K  [C_0402]  181.77 13.46 270 bottom
PCI35  0.22U_0402_16V7K  [C_0402]  181.55 15.2 90 bottom
PCI36  680P_0402_50V7K  [C_0402]  186.85 21.62 180 top
PCI37  1000P_0201_25V7K  [C_0201]  186.93 6.41 270 bottom
PCI38  1U_0402_25V6K  [C_0402]  186.17 6.83 270 bottom
PCI39  1000P_0201_25V7K  [C_0201]  171.24 8.88 270 top
PCI41  1000P_0201_25V7K  [C_0201]  177.99 8.96 270 top
PCI42  1000P_0201_25V7K  [C_0201]  178.55 8.96 270 top
PCI100  47U_0603_6.3V6M  [C_0603]  155.23 40.92 180 top
PCI101  47U_0603_6.3V6M  [C_0603]  155.23 39.72 180 top
PCI102  47U_0603_6.3V6M  [C_0603]  166.99 42.42 0 top
PCI103  47U_0603_6.3V6M  [C_0603]  159.92 42.42 0 top
PCI104  47U_0603_6.3V6M  [C_0603]  168.22 28.83 180 bottom
PCI105  47U_0603_6.3V6M  [C_0603]  159.87 39.54 0 top
PCI106  47U_0603_6.3V6M  [C_0603]  159.92 43.61 0 top
PCI107  22U_0603_6.3V6M  [C_0603]  173.85 29.51 180 bottom
PCI108  22U_0603_6.3V6M  [C_0603]  167.05 39.72 0 top
PCI109  22U_0603_6.3V6M  [C_0603]  155.23 37.33 180 top
PCI110  22U_0603_6.3V6M  [C_0603]  168.2 27.62 180 bottom
PCI111  22U_0603_6.3V6M  [C_0603]  166.03 42.42 180 top
PCI112  22U_0603_6.3V6M  [C_0603]  166.03 43.61 180 top
PCI113  22U_0603_6.3V6M  [C_0603]  155.23 38.53 180 top
PCI114  22U_0603_6.3V6M  [C_0603]  157.65 42.4 90 top
PCI115  22U_0603_6.3V6M  [C_0603]  156.46 42.4 90 top
PCI116  22U_0603_6.3V6M  [C_0603]  155.26 42.4 90 top
PCI117  22U_0603_6.3V6M  [C_0603]  154.07 42.4 90 top
PCI118  22U_0603_6.3V6M  [C_0603]  158.33 45.46 180 top
PCI119  22U_0603_6.3V6M  [C_0603]  155.28 46.19 270 top
PCI120  22U_0603_6.3V6M  [C_0603]  167.05 40.91 0 top
PCI121  22U_0603_6.3V6M  [C_0603]  178.58 29.51 180 bottom
PCI122  22U_0603_6.3V6M  [C_0603]  180.94 29.58 0 bottom
PCI123  330_B2_2.5VM_R9M  [C_B2]  180.59 27.33 180 bottom
PCI124  330_B2_2.5VM_R9M  [C_B2]  170.33 27.4 270 bottom
PCI125  330_B2_2.5VM_R9M  [C_B2]  174.32 27.29 180 bottom
PCI126  220U_D7_2VM_R6M  [C_EEFSS0D221R]  160.79 46.62 0 top
PCI127  220U_D7_2VM_R6M  [C_EEFSS0D221R]  170.11 23.54 0 top
PCI128  1U_0201_6.3V6M  [C_0201]  152.48 38.31 0 top
PCI129  1U_0201_6.3V6M  [C_0201]  163.09 36.04 180 top
PCI130  1U_0201_6.3V6M  [C_0201]  154.45 35.77 90 top
PCI131  1U_0201_6.3V6M  [C_0201]  153.88 35.73 90 top
PCI132  1U_0201_6.3V6M  [C_0201]  165.17 41.03 270 top
PCI133  1U_0201_6.3V6M  [C_0201]  165.73 41.02 270 top
PCI134  1U_0201_6.3V6M  [C_0201]  166.29 41.02 270 top
PCI135  1U_0201_6.3V6M  [C_0201]  159.57 41.02 270 top
PCI136  1U_0201_6.3V6M  [C_0201]  158.96 41.14 180 top
PCI137  1U_0201_6.3V6M  [C_0201]  158.96 40.58 180 top
PCI138  1U_0201_6.3V6M  [C_0201]  158.96 39.47 180 top
PCI139  1U_0201_6.3V6M  [C_0201]  157.08 36.05 0 top
PCI140  1U_0201_6.3V6M  [C_0201]  161.18 35.98 180 top
PCI141  1U_0201_6.3V6M  [C_0201]  158.96 40.02 180 top
PCI142  1U_0201_6.3V6M  [C_0201]  157.8 37.62 180 top
PCI143  1U_0201_6.3V6M  [C_0201]  155.07 36.01 0 top
PCI144  1U_0201_6.3V6M  [C_0201]  161.08 37.11 180 top
PCI145  1U_0201_6.3V6M  [C_0201]  152.91 43.22 180 top
PCI146  1U_0201_6.3V6M  [C_0201]  158.4 37.58 90 top
PCI147  1U_0201_6.3V6M  [C_0201]  156.04 37.07 0 top
PCI148  1U_0201_6.3V6M  [C_0201]  156.04 37.63 0 top
PCI149  1U_0201_6.3V6M  [C_0201]  152.48 37.2 0 top
PCI150  1U_0201_6.3V6M  [C_0201]  152.48 36.64 0 top
PCI151  1U_0201_6.3V6M  [C_0201]  152.91 42.66 180 top
PCI152  1U_0201_6.3V6M  [C_0201]  152.71 36.05 0 top
PCI153  1U_0201_6.3V6M  [C_0201]  159.05 36.02 180 top
PCI154  1U_0201_6.3V6M  [C_0201]  158.43 36.99 0 top
PCI155  1U_0201_6.3V6M  [C_0201]  156.17 45.81 90 top
PCI156  1U_0201_6.3V6M  [C_0201]  158.51 46.38 180 top
PCI157  1U_0201_6.3V6M  [C_0201]  158.51 44.55 180 top
PCI158  1U_0201_6.3V6M  [C_0201]  156.17 45.18 270 top
PCI159  1U_0201_6.3V6M  [C_0201]  164.61 41.02 270 top
PCI160  1U_0201_6.3V6M  [C_0201]  164.05 41.02 270 top
PCI161  1U_0201_6.3V6M  [C_0201]  163.49 41.02 270 top
PCI162  1U_0201_6.3V6M  [C_0201]  162.92 41.07 270 top
PCI163  22U_0603_6.3V6M  [C_0603]  185.02 26.39 90 bottom
PCI164  22U_0603_6.3V6M  [C_0603]  174.81 29.51 0 bottom
PCI165  22U_0603_6.3V6M  [C_0603]  186.24 26.4 90 bottom
PCI166  22U_0603_6.3V6M  [C_0603]  166.01 39.52 180 top
PCI167  22U_0603_6.3V6M  [C_0603]  166.99 43.61 0 top
PCI168  22U_0603_6.3V6M  [C_0603]  158.26 48.58 270 top
PCI169  22U_0603_6.3V6M  [C_0603]  157.06 48.58 270 top
PCI170  22U_0603_6.3V6M  [C_0603]  155.87 48.58 270 top
PCI171  22U_0603_6.3V6M  [C_0603]  154.06 46.19 270 top
PCI172  1U_0201_6.3V6M  [C_0201]  161.8 41.02 270 top
PCI173  1U_0201_6.3V6M  [C_0201]  161.24 41.02 270 top
PCI174  1U_0201_6.3V6M  [C_0201]  162.36 41.02 270 top
PCI175  1U_0201_6.3V6M  [C_0201]  160.68 41.02 270 top
PCI176  1U_0201_6.3V6M  [C_0201]  160.13 41.02 270 top
PCI177  1U_0201_6.3V6M  [C_0201]  157.82 37.05 180 top
PCI178  1U_0201_6.3V6M  [C_0201]  163.84 36.14 0 top
PCI179  1U_0201_6.3V6M  [C_0201]  152.48 37.75 0 top
PCI180  1U_0201_6.3V6M  [C_0201]  158.86 50.67 0 top
PCI181  1U_0201_6.3V6M  [C_0201]  158.86 51.24 0 top
PCI182  1U_0201_6.3V6M  [C_0201]  158.27 50.66 180 top
PCI183  1U_0201_6.3V6M  [C_0201]  158.27 51.24 180 top
PCI184  1U_0201_6.3V6M  [C_0201]  156.38 51.23 0 top
PCI185  1U_0201_6.3V6M  [C_0201]  156.37 50.67 0 top
PCI186  1U_0201_6.3V6M  [C_0201]  155.44 50.7 180 top
PCI187  1U_0201_6.3V6M  [C_0201]  155.44 51.25 180 top
PCI188  1U_0201_6.3V6M  [C_0201]  153.69 51.25 0 top
PCI189  1U_0201_6.3V6M  [C_0201]  153.03 51.25 180 top
PCI190  1U_0201_6.3V6M  [C_0201]  153.03 50.7 180 top
PCI191  47U_0603_6.3V6M  [C_0603]  158.84 42.4 90 top
PCI192  47U_0603_6.3V6M  [C_0603]  163.68 42.42 180 top
PCI193  47U_0603_6.3V6M  [C_0603]  163.68 43.61 180 top
PCI194  47U_0603_6.3V6M  [C_0603]  187.48 26.36 90 bottom
PCI195  47U_0603_6.3V6M  [C_0603]  163.63 39.52 180 top
PCI196  47U_0603_6.3V6M  [C_0603]  163.63 38.33 180 top
PCI197  47U_0603_6.3V6M  [C_0603]  156.21 40.9 0 top
PCI198  47U_0603_6.3V6M  [C_0603]  163.65 37.09 180 top
PCI199  47U_0603_6.3V6M  [C_0603]  166.05 37.08 180 top
PCI200  47U_0603_6.3V6M  [C_0603]  166.03 38.29 180 top
PCI201  47U_0603_6.3V6M  [C_0603]  159.85 38.33 0 top
PCI202  47U_0603_6.3V6M  [C_0603]  156.21 38.51 0 top
PCI203  47U_0603_6.3V6M  [C_0603]  156.21 39.7 0 top
PCI204  22U_0603_6.3V6M  [C_0603]  166.93 19.43 270 top
PCI205  22U_0603_6.3V6M  [C_0603]  165.74 19.43 270 top
PCI206  22U_0603_6.3V6M  [C_0603]  164.55 19.43 270 top
PCI207  22U_0603_6.3V6M  [C_0603]  163.35 19.43 270 top
PCM06  1000P_0402_25V8J  [C_0402]  200.4 57.78 0 top
PCM07  1U_0402_25V6K  [C_0402]  200.23 58.67 0 top
PCM17  0.1U_0402_25V6  [C_0402]  201.94 55.64 270 top
PCM18  10U_0603_25V6M  [C_0603]  190.56 68.7 90 bottom
PCM19  0.22U_0402_10V6K  [C_0402]  194.48 71.5 180 bottom
PCM20  1U_0402_16V6K  [C_0402]  192.65 71.49 180 bottom
PCM21  10U_0402_6.3V6M  [C_0402]  195.87 71.45 90 bottom
PCM22  0.1U_0402_10V7K  [C_0402]  190.08 66.64 180 bottom
PCM23  22U_0603_6.3V6M  [C_0603]  196.8 61.1 270 top
PCM24  22U_0603_6.3V6M  [C_0603]  194.41 61.1 270 top
PCM25  10U_0402_6.3V6M  [C_0402]  196.78 71.62 90 bottom
PCM26  2200P_0402_25V7K  [C_0402]  190.23 67.72 180 bottom
PCM27  0.22U_0402_16V7K  [C_0402]  196.72 68.75 90 bottom
PCM28  0.1U_0402_10V7K  [C_0402]  191.81 65.75 180 bottom
PCM29  22U_0603_6.3V6M  [C_0603]  195.61 61.1 270 top
PCM30  680P_0402_50V7K  [C_0402]  198.72 72.73 90 top
PCM31  22U_0603_6.3V6M  [C_0603]  198 61.1 270 top
PCM32  220P_0402_50V8J  [C_0402]  194.99 64.1 90 bottom
PCV01  33U_B3_16VM_R45M  [C_B3]  52.75 61.86 0 top
PCV02  33U_B3_16VM_R45M  [C_B3]  49.96 61.83 180 top
PCV03  33U_B3_16VM_R45M  [C_B3]  49.95 65.06 180 top
PCV04  33U_B3_16VM_R45M  [C_B3]  49.96 68.26 180 top
PCV8  33U_B3_16VM_R45M  [C_B3]  52.75 68.25 0 top
PCV9  10U_0603_25V6M  [C_0603]  52.15 72.98 270 bottom
PCV10  1U_0402_25V6K  [C_0402]  57.64 73.04 90 bottom
PCV11  10U_0603_25V6M  [C_0603]  52.15 72.98 270 top
PCV12  1U_0402_25V6K  [C_0402]  56.27 75.28 180 bottom
PCV13  1U_0402_25V6K  [C_0402]  57.14 75.24 90 bottom
PCV14  220U_D7_2VM_R6M  [C_EEFSS0D221R]  110.89 70.19 90 top
PCV15  680P_0402_50V7K  [C_0402]  60.94 76.3 90 top
PCV16  4.7U_0603_6.3VAK  [C_0603]  112.79 66.04 180 top
PCV17  4.7U_0603_6.3VAK  [C_0603]  113.73 64.92 0 top
PCV18  4.7U_0603_6.3VAK  [C_0603]  116.37 63.86 45 bottom
PCV19  4.7U_0603_6.3VAK  [C_0603]  109.05 65.98 0 top
PCV20  4.7U_0603_6.3VAK  [C_0603]  109.05 64.78 0 top
PCV21  4.7U_0603_6.3VAK  [C_0603]  109.05 67.17 0 top
PCV22  4.7U_0603_6.3VAK  [C_0603]  112.79 63.65 180 top
PCV23  4.7U_0603_6.3VAK  [C_0603]  116.37 70.4 270 top
PCV24  4.7U_0603_6.3VAK  [C_0603]  103.19 55.03 270 top
PCV25  4.7U_0603_6.3VAK  [C_0603]  104.7 55.08 270 top
PCV26  4.7U_0603_6.3VAK  [C_0603]  103.38 69.75 180 top
PCV27  4.7U_0603_6.3VAK  [C_0603]  103.38 70.97 180 top
PCV28  1U_0402_6.3VAK  [C_0402]  107.86 54.35 270 top
PCV29  1U_0402_6.3VAK  [C_0402]  108.17 63.36 180 top
PCV30  1U_0402_6.3VAK  [C_0402]  108.8 55.25 0 top
PCV31  1U_0402_6.3VAK  [C_0402]  106.97 54.35 270 top
PCV32  1U_0402_6.3VAK  [C_0402]  108.78 54.37 270 top
PCV33  22U_0603_6.3V6M  [C_0603]  105.9 54.97 270 top
PCV34  10U_0603_25V6M  [C_0603]  52.21 65.53 270 bottom
PCV35  1U_0402_25V6K  [C_0402]  56.21 67.78 180 bottom
PCV37  1U_0402_25V6K  [C_0402]  57.66 65.46 90 bottom
PCV38  10U_0603_25V6M  [C_0603]  53.45 65.89 0 top
PCV39  1U_0402_25V6K  [C_0402]  57.08 67.75 90 bottom
PCV41  680P_0402_50V7K  [C_0402]  62.75 64.64 90 top
PCV42  0.01U_0402_50V7K  [C_0402]  43.34 64.72 0 top
PCV43  680P_0402_50V7K  [C_0402]  37.23 64.52 90 top
PCV44  1U_0402_6.3V6K  [C_0402]  43.02 65.89 0 top
PCV45  680P_0402_50V7K  [C_0402]  38.54 60.72 270 top
PCV46  1U_0402_6.3V6K  [C_0402]  41.09 60.34 270 top
PCV47  1U_0402_6.3V6K  [C_0402]  40.19 60.35 270 top
PCV48  4.7U_0603_25V6K  [C_0603]  40.57 67.97 270 top
PCV50  220U_D7_2VM_R6M  [C_EEFSS0D221R]  64.25 73.3 180 top
PCV51  220U_D7_2VM_R6M  [C_EEFSS0D221R]  64.26 68.59 180 top
PCV52  220U_D7_2VM_R6M  [C_EEFSS0D221R]  106.2 70.19 90 top
PCV53  22U_0603_6.3V6M  [C_0603]  109.05 63.58 0 top
PCV54  22U_0603_6.3V6M  [C_0603]  113.73 63.73 0 top
PCV55  22U_0603_6.3V6M  [C_0603]  113.73 69.71 0 top
PCV56  4.7U_0603_6.3V6K  [C_0603]  113.73 70.91 0 top
PCV57  4.7U_0603_6.3V6K  [C_0603]  112.79 67.24 180 top
PCV58  4.7U_0603_6.3V6K  [C_0603]  112.13 68.09 45 bottom
PCV59  4.7U_0603_6.3V6K  [C_0603]  109.58 70.63 45 bottom
PCV60  10U_0603_6.3VAM  [C_0603]  114.67 65.56 45 bottom
PCV61  10U_0603_6.3VAM  [C_0603]  110.43 69.79 45 bottom
PCV62  10U_0603_6.3VAM  [C_0603]  115.52 64.71 45 bottom
PCV63  10U_0603_6.3VAM  [C_0603]  112.97 67.25 45 bottom
PCV64  10U_0603_6.3VAM  [C_0603]  113.82 66.4 45 bottom
PCV65  10U_0603_6.3VAM  [C_0603]  108.1 67.68 180 top
PCV66  10U_0603_6.3VAM  [C_0603]  113.73 67.32 0 top
PCV67  10U_0603_6.3VAM  [C_0603]  113.73 66.12 0 top
PCV68  10U_0603_6.3VAM  [C_0603]  112.79 64.84 180 top
PCV69  10U_0603_6.3VAM  [C_0603]  111.28 68.94 45 bottom
PCV70  10U_0603_6.3VAM  [C_0603]  113.73 68.51 0 top
PCV71  1000P_0402_25V8J  [C_0402]  43.48 69.52 180 top
PCV72  1U_0402_25V6K  [C_0402]  43.48 68.64 180 top
PCW12  0.1U_0402_25V6  [C_0402]  61.49 59.53 270 top
PCW16  10U_0603_25V6M  [C_0603]  68.67 59.21 0 top
PCW17  680P_0402_50V7K  [C_0402]  74.21 56.53 90 bottom
PCW18  0.1U_0402_10V7K  [C_0402]  72.59 52.54 270 top
PCW19  0.1U_0402_25V6  [C_0402]  69.18 58.05 0 top
PCW20  2200P_0402_50V7K  [C_0402]  71.02 56.33 0 top
PCW21  10U_0603_25V6M  [C_0603]  72.42 55.15 180 top
PCW22  2.2U_0402_6.3V6M  [C_0402]  65.18 53.85 270 top
PCW23  22U_0603_6.3V6M  [C_0603]  75.66 45.23 315 top
PCW24  330P_0402_50V7K  [C_0402]  63.39 55.02 0 top
PCW26  10U_0603_25V6M  [C_0603]  72.48 57.56 180 top
PCW27  22U_0603_6.3V6M  [C_0603]  76.68 53.94 135 top
PCW28  22U_0603_6.3V6M  [C_0603]  76.51 46.09 315 top
PCW29  22U_0603_6.3V6M  [C_0603]  77.36 46.94 315 top
PCW30  22U_0603_6.3V6M  [C_0603]  76.7 48.96 135 top
PCW31  22U_0603_6.3V6M  [C_0603]  78.23 47.77 315 top
PCW32  0.1U_0402_25V6  [C_0402]  71.08 58.76 0 top
PCW33  1000P_0402_25V8J  [C_0402]  67.12 60.72 270 top
PCW34  1U_0402_25V6K  [C_0402]  66.11 60.72 270 top
PCW35  1U_0402_6.3V6K  [C_0402]  62.76 53.95 270 top
PCW36  2200P_0201_10V6K  [C_0201]  75.23 43.45 270 top
PCW37  0.1U_0201_6.3V6K  [C_0201]  75.36 44.25 315 top
PCW38  100P_0201_25V7K  [C_0201]  79.44 48.24 315 top
PCZ01  0.1U_0402_25V6  [C_0402]  159.33 16.51 90 bottom
PCZ02  0.1U_0402_25V6  [C_0402]  165.26 21.26 90 bottom
PCZ03  1U_0402_10V6K  [C_0402]  152.96 16.51 90 bottom
PCZ04  330P_0402_50V8J  [C_0402]  157.94 28.97 180 bottom
PCZ05  180P_0402_50V8J  [C_0402]  158.3 28.09 270 bottom
PCZ06  33P_0402_50V8J  [C_0402]  159.95 28.09 270 bottom
PCZ07  1U_0603_10V6K  [C_0603]  154.77 17.87 270 bottom
PCZ08  0.01U_0402_16V7K  [C_0402]  153.56 28.8 0 bottom
PCZ09  0.01U_0402_16V7K  [C_0402]  150.17 25.4 90 bottom
PCZ10  0.01U_0402_16V7K  [C_0402]  150.12 22.12 90 bottom
PCZ11  4.7U_0603_10V6K  [C_0603]  158.28 17.87 270 bottom
PCZ12  1U_0603_10V6K  [C_0603]  161.37 25.94 0 bottom
PCZ13  0.01U_0402_50V7K  [C_0402]  150.54 17.42 270 bottom
PD5  -  [CEST523NC5VB_SOT-523-3]  107.75 6.21 180 top
PD6  -  [CEST523NC5VB_SOT-523-3]  111.72 10.42 270 top
PDB01  -  [RB751V-40_SOD323-2]  189.13 17.77 270 bottom
PDB02  -  [RB751V-40_SOD323-2]  190.76 17.77 270 bottom
PDB05  -  [SMF4L22A_SOD123FL2]  184.63 11.41 270 top
PJP1  -  [JUMP_43X118]  77.86 16.75 180 top
PJP302  -  [JUMP_43X118]  28.72 14.82 0 top
PJP501  PAD-OPEN 4X4M  [JUMP_43X118]  27.02 23.61 0 top
PJP1800  -  [JUMP_43X79]  77.86 26.77 90 top
PJPDC1  ACES_50290-0050N-001  [ACES_50290-0050N-001_5P-T]  81.06 17.41 0 top
PJPF01  -  [JUMP_43X39]  119.79 45.58 180 bottom
PJPF02  -  [JUMP_43X39]  108.24 43.66 135 bottom
PJPH01  PAD-OPEN 4X4M  [JUMP_43X118]  134.54 27.47 90 bottom
PJPM3  -  [JUMP_43X39]  195.8 70.71 180 top
PJPM4  -  [JUMP_43X118]  183.92 61.02 180 top
PJPW4  -  [JUMP_43X118]  77.91 50.82 45 top
PL4  3A_Z120_40M_0603_2P  [3A_Z120_0603_2P]  101.47 10.52 90 top
PL5  3A_Z120_40M_0603_2P  [3A_Z120_0603_2P]  102.9 10.52 90 top
PL7  3A_Z120_40M_0603_2P  [3A_Z120_0603_2P]  104.32 10.52 90 top
PL8  3A_Z120_40M_0603_2P  [3A_Z120_0603_2P]  105.74 10.52 90 top
PL301  1.5UH_MMD-06AEI1R5M-M1L_6.5A_20%  [MAG_MMD-06AEI1R5M-M1L_2P]  17.9 14.78 0 bottom
PL311  3A_Z120_40M_0603_2P  [3A_Z120_0603_2P]  8.64 14.43 0 bottom
PL312  3A_Z120_40M_0603_2P  [3A_Z120_0603_2P]  8.65 15.86 0 bottom
PL501  1.5UH_MMD-06AH-1R5M-X2_6.5A_20%  [MAG_MMD-06AH-1R5M-X2_2P]  18.18 22.04 0 bottom
PL511  -  [5A_Z80_0805_2P]  8.99 21.86 0 bottom
PL1801  1UH_FDSD0412-H-1R0M-P3_3.3A_20%  [TOKO_FDSD0412-H-1R0M-P3_2P]  70.05 25.25 0 top
PL1811  3A_Z120_40M_0603_2P  [3A_Z120_0603_2P]  71.45 12.91 90 top
PLA01  0.33UH_MMD-05CZ-R33M-V1L_13.7A_20%  [MAG_MMD-05CZ-R33M-V1L_2P]  142.69 24.75 0 bottom
PLA11  -  [5A_Z80_0805_2P]  137.52 17.49 0 bottom
PLB01  1UH_PCMB103T-1R0MS_13A_20%  [CYNTE_PCMB103T-1R0MS_2P]  197.85 10.81 0 bottom
PLB11  1UH_MLV-FY12N1R0M-C1L_4.9A_20%  [MAG_MLV-FY12N1R0M-C1L_2P]  186.35 10.63 0 top
PLG01  0.15UH_NA__35A_20%  [CYNTE_PCME063T-R15MS0R907_2P]  197.4 39.64 180 bottom
PLG11  -  [5A_Z80_0805_2P]  204.24 31.12 90 bottom
PLG12  -  [5A_Z80_0805_2P]  206.02 31.12 90 bottom
PLH01  0.47UH 20% MMD-05CZ-R47MEV1L 12.2A  [MAG_MMD-05CZ-R33M-V1L_2P]  133.14 23.38 0 bottom
PLH11  -  [5A_Z80_0805_2P]  136.16 17.49 180 bottom
PLI01  0.15UH_NA__35A_20%  [L_7X7X3_M]  169.56 17.7 90 bottom
PLI02  0.15UH_NA__35A_20%  [L_7X7X3_M]  177.05 17.7 90 bottom
PLI03  0.15UH_NA__35A_20%  [L_7X7X3_M]  184.55 17.7 90 bottom
PLI11  -  [5A_Z80_0805_2P]  181.19 6.61 90 bottom
PLI12  -  [5A_Z80_0805_2P]  182.97 6.61 90 bottom
PLI13  -  [5A_Z80_0805_2P]  184.75 6.61 90 bottom
PLM12  -  [5A_Z80_0805_2P]  200.61 55.04 90 top
PLM13  1UH_CMLB051B-1R0MS_5.5A_20%  [CYNTE_CMLB051B-1R0MS_2P]  196.42 67.77 270 top
PLV01  0.15UH_NA__35A_20%  [CYNTE_PCME063T-R15MS0R907_2P]  60.15 73.08 0 bottom
PLV02  0.15UH_NA__35A_20%  [CYNTE_PCME063T-R15MS0R907_2P]  60.15 65.16 0 bottom
PLV03  -  [5A_Z80_0805_2P]  48.58 70.81 0 top
PLV04  -  [5A_Z80_0805_2P]  48.58 72.63 0 top
PLW12  1UH_MHCI06012-1R0M-R8A_6A_20%  [CHILI_MHCI06012-1R0M-R8A_2P]  69.6 50.52 270 top
PLW13  -  [5A_Z80_0805_2P]  68.25 60.75 0 top
PQ1  -  [FDV301N-G_SOT23-3]  115.53 11.07 0 top
PQ2  -  [LMBT3904WT1G_SC70-3]  119.47 15.47 180 top
PQ100  -  [2N7002KDW_SOT363-6]  101.24 27.35 270 top
PQ501  2N7002KW_SOT323-3  [DMN65D8LW-7_SOT323-3]  48.87 6.62 270 top
PQ1402  2N7002KW_SOT323-3  [DMN65D8LW-7_SOT323-3]  108.29 17.74 90 top
PQB01  -  [AON6994_DFN5X6D-8-7]  190.24 11.92 0 bottom
PQB02  -  [AON6994_DFN5X6D-8-7]  203.05 18.79 90 bottom
PQB03  -  [AON7409_DFN8-5]  95.17 12.58 270 top
PQB04  2N7002KW_SOT323-3  [DMN65D8LW-7_SOT323-3]  189.59 26.21 0 bottom
PQB12  -  [LMUN5113T1G_SOT323-3]  103.08 6.3 0 top
PQB13  LMUN5236T1G NPN SOT323-3  [LMUN5113T1G_SOT323-3]  105.53 7.91 180 top
PR1  33_0402_5%  [R_0402]  114.59 14.85 0 top
